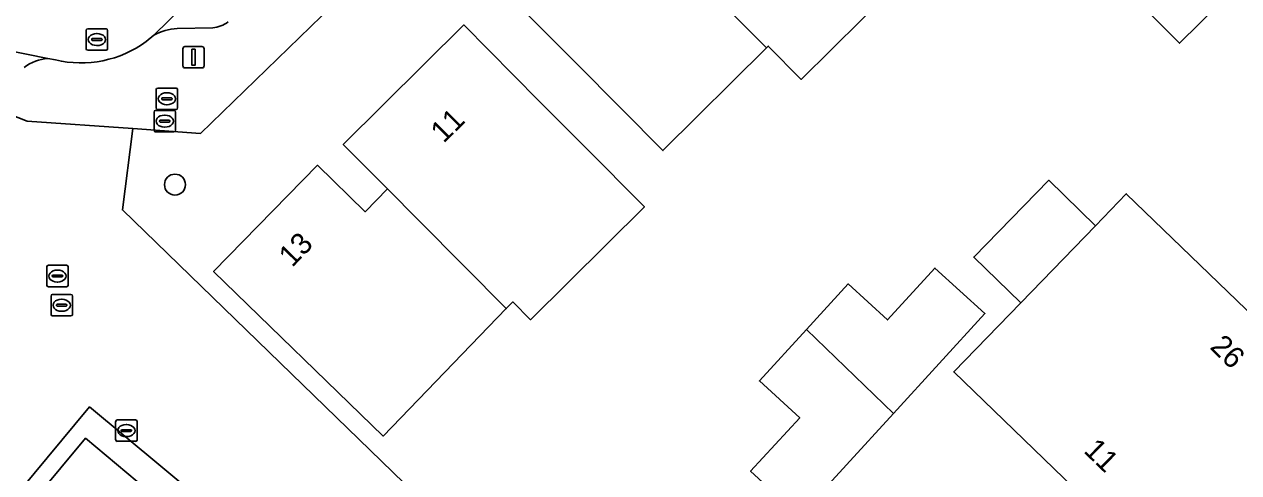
# Model space of a CAD drawing. Extents: x 161772 to 163126, y 383092 to 383917.
# Drawn here: x 162030.6 to 162087.2, y 383341.2 to 383362.1 of the extents above; entities that cross this region are included whole.
import ezdxf

# ---------------------------------------------------------------- set-up
doc = ezdxf.new("R2010")
doc.units = 0
for name, color, linetype in [('IMGEO_Boom', 7, 'Continuous'), ('IMGEO_Brandkraan', 7, 'Continuous'), ('IMGEO_Erf', 7, 'Continuous'), ('IMGEO_Kolk', 7, 'Continuous'), ('IMGEO_Lichtmast', 7, 'Continuous'), ('IMGEO_Pand', 7, 'Continuous'), ('IMGEO_Pand_nummerreeks', 7, 'Continuous'), ('IMGEO_Parkeervlak_open', 7, 'Continuous'), ('IMGEO_Rijbaan_lokaal_open', 7, 'Continuous'), ('IMGEO_Rioolput', 7, 'Continuous'), ('IMGEO_Voetpad_gesloten', 7, 'Continuous')]:
    doc.layers.add(name, color=color, linetype=linetype)

msp = doc.modelspace()

# ---------------------------------------------------------------- linework, layer by layer
at = {"layer": 'IMGEO_Boom'}
msp.add_circle((162037.581, 383354.637), 0.489, dxfattribs=at)
at = {"layer": 'IMGEO_Brandkraan'}
for p, q in [((162036.702, 383358.217), (162036.702, 383359.069)), ((162036.777, 383359.143), (162037.629, 383359.143)), ((162037.19, 383358.923), (162037.215, 383358.923)), ((162037.703, 383359.069), (162037.703, 383358.217)), ((162037.629, 383358.143), (162036.777, 383358.143)), ((162036.961, 383358.637), (162036.961, 383358.649)), ((162037.399, 383358.6), (162037.001, 383358.6)), ((162037.004, 383358.686), (162037.402, 383358.686)), ((162037.213, 383358.363), (162037.188, 383358.363)), ((162037.445, 383358.649), (162037.445, 383358.637)), ((162036.603, 383357.173), (162036.603, 383358.025)), ((162036.678, 383358.099), (162037.53, 383358.099)), ((162036.862, 383357.593), (162036.862, 383357.605)), ((162036.905, 383357.642), (162037.303, 383357.642)), ((162037.091, 383357.879), (162037.116, 383357.879)), ((162037.346, 383357.605), (162037.346, 383357.593)), ((162037.604, 383358.025), (162037.604, 383357.173)), ((162037.53, 383357.099), (162036.678, 383357.099)), ((162037.3, 383357.556), (162036.902, 383357.556)), ((162037.114, 383357.319), (162037.089, 383357.319))]:
    msp.add_line(p, q, dxfattribs=at)
for points in [[(162036.702, 383358.217), (162036.702, 383359.069)], [(162036.777, 383359.143), (162037.629, 383359.143)], [(162037.703, 383359.069), (162037.703, 383358.217)], [(162037.629, 383358.143), (162036.777, 383358.143)], [(162036.603, 383357.173), (162036.603, 383358.025)], [(162036.678, 383358.099), (162037.53, 383358.099)], [(162037.604, 383358.025), (162037.604, 383357.173)], [(162037.53, 383357.099), (162036.678, 383357.099)]]:
    msp.add_lwpolyline(points, dxfattribs=at)
for centre, radius, start, end in [((162036.779, 383359.067), 0.0765, 91.552, 178.448), ((162036.779, 383359.067), 0.0765, 91.552, 178.448), ((162037.627, 383359.067), 0.0765, 1.552, 88.448), ((162037.627, 383359.067), 0.0765, 1.552, 88.448), ((162036.779, 383358.219), 0.0765, 181.552, 268.448), ((162036.779, 383358.219), 0.0765, 181.552, 268.448), ((162037.001, 383358.646), 0.0403, 85.8775, 175.7526), ((162036.998, 383358.636), 0.0366, 178.938, 274.7102), ((162037.402, 383358.643), 0.043, 264.8664, 352.4533), ((162037.406, 383358.648), 0.0386, 1.7309, 96.639), ((162037.627, 383358.219), 0.0765, 271.552, 358.448), ((162037.627, 383358.219), 0.0765, 271.552, 358.448), ((162036.68, 383358.023), 0.0765, 91.552, 178.448), ((162036.68, 383358.023), 0.0765, 91.552, 178.448), ((162036.902, 383357.602), 0.0403, 85.8775, 175.7526), ((162036.899, 383357.592), 0.0366, 178.938, 274.7102), ((162037.303, 383357.599), 0.043, 264.8664, 352.4533), ((162037.307, 383357.604), 0.0386, 1.7309, 96.639), ((162037.528, 383358.023), 0.0765, 1.552, 88.448), ((162037.528, 383358.023), 0.0765, 1.552, 88.448), ((162036.68, 383357.175), 0.0765, 181.552, 268.448), ((162036.68, 383357.175), 0.0765, 181.552, 268.448), ((162037.528, 383357.175), 0.0765, 271.552, 358.448), ((162037.528, 383357.175), 0.0765, 271.552, 358.448)]:
    msp.add_arc(centre, radius, start, end, dxfattribs=at)
for centre, major_axis, ratio, start_param, end_param in [((162037.189, 383358.643), (-0.387, 0.002), 0.722429, 4.712389, 7.853982), ((162037.214, 383358.643), (-0.39, 0.002), 0.717154, 1.570796, 4.712389), ((162037.09, 383357.599), (-0.387, 0.002), 0.722429, 4.712389, 7.853982), ((162037.115, 383357.599), (-0.39, 0.002), 0.717154, 1.570796, 4.712389)]:
    msp.add_ellipse(centre, major_axis=major_axis, ratio=ratio, start_param=start_param, end_param=end_param, dxfattribs=at)
at = {"layer": 'IMGEO_Erf'}
for points in [[(162085.05, 383335.095), (162085.636, 383334.487), (162109.459, 383358.96), (162108.772, 383359.637), (162097.704, 383370.546), (162075.222, 383392.703), (162064.395, 383381.925), (162038.775, 383357.03), (162035.617, 383357.251), (162035.13, 383353.454), (162066.087, 383323.385), (162066.709, 383324.02), (162059.456, 383331.069), (162065.31, 383337.087), (162065.453, 383336.949), (162072.586, 383330.051), (162076.509, 383326.257)], [(162082.301, 383363.348), (162084.152, 383365.186), (162086.251, 383363.073), (162084.4, 383361.234)], [(162047.282, 383342.905), (162039.377, 383350.576), (162044.228, 383355.54), (162046.445, 383353.374), (162047.48, 383354.434), (162045.42, 383356.508), (162051.035, 383362.086), (162054.544, 383358.552), (162056.667, 383356.415), (162059.455, 383353.606), (162054.148, 383348.335), (162053.322, 383349.167), (162053.021, 383348.855)], [(162074.803, 383351.259), (162078.297, 383354.84), (162080.471, 383352.719), (162081.913, 383354.211), (162093.087, 383343.412), (162085.05, 383335.095), (162073.876, 383345.894), (162076.995, 383349.121)], [(162075.322, 383348.619), (162071.07, 383343.965), (162066.692, 383339.172), (162064.408, 383341.259), (162066.693, 383343.76), (162064.816, 383345.474), (162067.017, 383347.884), (162068.953, 383350.003), (162070.79, 383348.325), (162072.998, 383350.742)], [(162033.597, 383344.262), (162019.25, 383326.968), (162019.834, 383326.482), (162033.413, 383342.802), (162044.491, 383333.503), (162045.324, 383334.504)]]:
    msp.add_lwpolyline(points, close=True, dxfattribs=at)
msp.add_lwpolyline([(162071.005, 383363.761), (162066.764, 383359.549), (162065.225, 383361.098), (162065.147, 383361.021), (162060.32, 383356.227), (162058.387, 383358.173), (162056.238, 383360.337), (162052.746, 383363.85)], dxfattribs=at)
at = {"layer": 'IMGEO_Kolk'}
for p, q in [((162034.816, 383342.733), (162034.816, 383343.585)), ((162034.891, 383343.659), (162035.743, 383343.659)), ((162035.304, 383343.439), (162035.329, 383343.439)), ((162035.817, 383343.585), (162035.817, 383342.733)), ((162035.075, 383343.153), (162035.075, 383343.165)), ((162035.513, 383343.116), (162035.115, 383343.116)), ((162035.118, 383343.202), (162035.516, 383343.202)), ((162035.327, 383342.879), (162035.302, 383342.879)), ((162035.559, 383343.165), (162035.559, 383343.153)), ((162035.743, 383342.659), (162034.891, 383342.659))]:
    msp.add_line(p, q, dxfattribs=at)
for points in [[(162034.816, 383342.733), (162034.816, 383343.585)], [(162034.891, 383343.659), (162035.743, 383343.659)], [(162035.817, 383343.585), (162035.817, 383342.733)], [(162035.743, 383342.659), (162034.891, 383342.659)]]:
    msp.add_lwpolyline(points, dxfattribs=at)
for centre, radius, start, end in [((162034.893, 383343.583), 0.0765, 91.552, 178.448), ((162034.893, 383343.583), 0.0765, 91.552, 178.448), ((162035.741, 383343.583), 0.0765, 1.552, 88.448), ((162035.741, 383343.583), 0.0765, 1.552, 88.448), ((162035.115, 383343.162), 0.0403, 85.8775, 175.7526), ((162035.112, 383343.152), 0.0366, 178.938, 274.7102), ((162035.516, 383343.159), 0.043, 264.8664, 352.4533), ((162035.52, 383343.164), 0.0386, 1.7309, 96.639), ((162034.893, 383342.735), 0.0765, 181.552, 268.448), ((162034.893, 383342.735), 0.0765, 181.552, 268.448), ((162035.741, 383342.735), 0.0765, 271.552, 358.448), ((162035.741, 383342.735), 0.0765, 271.552, 358.448)]:
    msp.add_arc(centre, radius, start, end, dxfattribs=at)
for centre, major_axis, ratio, start_param, end_param in [((162035.303, 383343.159), (-0.387, 0.002), 0.722429, 4.712389, 7.853982), ((162035.328, 383343.159), (-0.39, 0.002), 0.717154, 1.570796, 4.712389)]:
    msp.add_ellipse(centre, major_axis=major_axis, ratio=ratio, start_param=start_param, end_param=end_param, dxfattribs=at)
at = {"layer": 'IMGEO_Lichtmast'}
for p, q in [((162037.947, 383360.18), (162037.947, 383360.98)), ((162037.947, 383360.98), (162037.947, 383360.18)), ((162038.047, 383361.08), (162038.837, 383361.08)), ((162038.837, 383361.08), (162038.047, 383361.08)), ((162038.937, 383360.98), (162038.937, 383360.18)), ((162038.937, 383360.18), (162038.937, 383360.98)), ((162038.837, 383360.08), (162038.047, 383360.08)), ((162038.047, 383360.08), (162038.837, 383360.08))]:
    msp.add_line(p, q, dxfattribs=at)
msp.add_lwpolyline([(162038.367, 383360.955), (162038.517, 383360.955), (162038.517, 383360.205), (162038.367, 383360.205), (162038.367, 383360.955)], dxfattribs=at)
for centre, start, end in [((162038.047, 383360.98), 90, 180), ((162038.047, 383360.98), 90, 180), ((162038.837, 383360.98), 0, 90), ((162038.837, 383360.98), 360, 90), ((162038.047, 383360.18), 180, 270), ((162038.047, 383360.18), 180, 270), ((162038.837, 383360.18), 270, 0), ((162038.837, 383360.18), 270, 0)]:
    msp.add_arc(centre, 0.1, start, end, dxfattribs=at)
at = {"layer": 'IMGEO_Pand'}
for points in [[(162068.261, 383367.9), (162062.636, 383373.673), (162057.56, 383368.632), (162065.147, 383361.021), (162065.225, 383361.098), (162066.764, 383359.549), (162071.005, 383363.761), (162071.659, 383364.412)], [(162057.56, 383368.632), (162052.746, 383363.85), (162056.238, 383360.337), (162058.387, 383358.173), (162060.32, 383356.227), (162065.147, 383361.021)], [(162086.251, 383363.073), (162084.152, 383365.186), (162082.301, 383363.348), (162084.4, 383361.234)], [(162056.667, 383356.415), (162054.544, 383358.552), (162051.035, 383362.086), (162045.42, 383356.508), (162047.48, 383354.434), (162048.944, 383352.961), (162051.052, 383350.838), (162053.021, 383348.855), (162053.322, 383349.167), (162054.148, 383348.335), (162059.455, 383353.606)], [(162051.052, 383350.838), (162048.944, 383352.961), (162047.48, 383354.434), (162046.445, 383353.374), (162044.228, 383355.54), (162039.377, 383350.576), (162047.282, 383342.905), (162053.021, 383348.855)], [(162080.471, 383352.719), (162078.297, 383354.84), (162074.803, 383351.259), (162076.995, 383349.121)], [(162081.913, 383354.211), (162080.471, 383352.719), (162076.995, 383349.121), (162073.876, 383345.894), (162085.05, 383335.095), (162093.087, 383343.412)], [(162071.07, 383343.965), (162075.322, 383348.619), (162072.998, 383350.742), (162070.79, 383348.325), (162068.953, 383350.003), (162067.017, 383347.884)], [(162071.07, 383343.965), (162067.017, 383347.884), (162064.816, 383345.474), (162066.693, 383343.76), (162064.408, 383341.259), (162066.692, 383339.172)], [(162042.175, 383330.708), (162042.699, 383331.34), (162044.491, 383333.503), (162033.413, 383342.802), (162019.834, 383326.482), (162024.353, 383322.748), (162026.638, 383320.859), (162031.017, 383317.241), (162032.919, 383319.537)]]:
    msp.add_lwpolyline(points, close=True, dxfattribs=at)
at = {"layer": 'IMGEO_Parkeervlak_open'}
for points in [[(162069.402, 383393.751), (162036.595, 383361.608)], [(162031.651, 383360.514), (161994.524, 383368.077), (161993.858, 383368.213)], [(162037.678, 383361.928), (162039.344, 383361.959)]]:
    msp.add_lwpolyline(points, dxfattribs=at)
for centre, radius, start, end in [((162039.229, 383363.336), 1.382, 274.7736, 306.7612), ((162037.889, 383359.22), 2.716, 94.4626, 118.4597), ((162031.784, 383358.483), 2.036, 93.7359, 127.0196)]:
    msp.add_arc(centre, radius, start, end, dxfattribs=at)
at = {"layer": 'IMGEO_Rijbaan_lokaal_open'}
for points in [[(162036.245, 383361.319), (162036.595, 383361.608), (162069.402, 383393.751)], [(162031.731, 383363.861), (162026.624, 383364.907), (162022.901, 383365.67), (161995.201, 383371.459), (161994.524, 383368.077), (162031.651, 383360.514), (162032.009, 383360.453)], [(162066.087, 383323.385), (162035.13, 383353.454), (162035.617, 383357.251), (162030.694, 383357.595), (162029.829, 383357.939), (162027.077, 383344.535), (162026.145, 383344.722), (162012.665, 383328.248)]]:
    msp.add_lwpolyline(points, dxfattribs=at)
msp.add_lwpolyline([(162021.848, 383319.686), (162024.353, 383322.748), (162019.834, 383326.482), (162019.25, 383326.968), (162033.597, 383344.262), (162045.324, 383334.504), (162044.491, 383333.503), (162042.699, 383331.34), (162042.175, 383330.708), (162042.065, 383329.499), (162041.991, 383329.019), (162041.464, 383328.268), (162040.242, 383327.129), (162039.15, 383325.806), (162037.784, 383323.976), (162036.394, 383322.553), (162035.787, 383321.748), (162035.018, 383320.343), (162034.547, 383319.954), (162034.107, 383319.606), (162032.919, 383319.537), (162031.017, 383317.241), (162026.638, 383320.859), (162024.174, 383317.796)], close=True, dxfattribs=at)
msp.add_arc((162033.188, 383365.477), 5.161, 256.7896, 306.3189, dxfattribs=at)
at = {"layer": 'IMGEO_Rioolput'}
for p, q in [((162033.44, 383360.98), (162033.44, 383361.832)), ((162033.515, 383361.906), (162034.367, 383361.906)), ((162033.928, 383361.686), (162033.953, 383361.686)), ((162034.441, 383361.832), (162034.441, 383360.98)), ((162033.699, 383361.4), (162033.699, 383361.412)), ((162034.137, 383361.363), (162033.739, 383361.363)), ((162033.742, 383361.449), (162034.14, 383361.449)), ((162033.951, 383361.126), (162033.926, 383361.126)), ((162034.183, 383361.412), (162034.183, 383361.4)), ((162034.367, 383360.906), (162033.515, 383360.906)), ((162031.604, 383349.945), (162031.604, 383350.797)), ((162031.679, 383350.871), (162032.531, 383350.871)), ((162032.605, 383350.797), (162032.605, 383349.945)), ((162031.863, 383350.365), (162031.863, 383350.377)), ((162032.301, 383350.328), (162031.903, 383350.328)), ((162031.906, 383350.414), (162032.304, 383350.414)), ((162032.092, 383350.651), (162032.117, 383350.651)), ((162032.347, 383350.377), (162032.347, 383350.365)), ((162032.531, 383349.871), (162031.679, 383349.871)), ((162032.115, 383350.091), (162032.09, 383350.091)), ((162031.803, 383348.583), (162031.803, 383349.435)), ((162031.878, 383349.509), (162032.73, 383349.509)), ((162032.291, 383349.289), (162032.316, 383349.289)), ((162032.804, 383349.435), (162032.804, 383348.583)), ((162032.73, 383348.509), (162031.878, 383348.509)), ((162032.062, 383349.003), (162032.062, 383349.015)), ((162032.5, 383348.966), (162032.102, 383348.966)), ((162032.105, 383349.052), (162032.503, 383349.052)), ((162032.314, 383348.729), (162032.289, 383348.729)), ((162032.546, 383349.015), (162032.546, 383349.003))]:
    msp.add_line(p, q, dxfattribs=at)
for points in [[(162033.44, 383360.98), (162033.44, 383361.832)], [(162033.515, 383361.906), (162034.367, 383361.906)], [(162034.441, 383361.832), (162034.441, 383360.98)], [(162034.367, 383360.906), (162033.515, 383360.906)], [(162031.604, 383349.945), (162031.604, 383350.797)], [(162031.679, 383350.871), (162032.531, 383350.871)], [(162032.605, 383350.797), (162032.605, 383349.945)], [(162032.531, 383349.871), (162031.679, 383349.871)], [(162031.803, 383348.583), (162031.803, 383349.435)], [(162031.878, 383349.509), (162032.73, 383349.509)], [(162032.804, 383349.435), (162032.804, 383348.583)], [(162032.73, 383348.509), (162031.878, 383348.509)]]:
    msp.add_lwpolyline(points, dxfattribs=at)
for centre, radius, start, end in [((162033.517, 383361.83), 0.0765, 91.552, 178.448), ((162033.517, 383361.83), 0.0765, 91.552, 178.448), ((162034.365, 383361.83), 0.0765, 1.552, 88.448), ((162034.365, 383361.83), 0.0765, 1.552, 88.448), ((162033.517, 383360.982), 0.0765, 181.552, 268.448), ((162033.517, 383360.982), 0.0765, 181.552, 268.448), ((162033.739, 383361.409), 0.0403, 85.8775, 175.7526), ((162033.736, 383361.399), 0.0366, 178.938, 274.7102), ((162034.14, 383361.406), 0.043, 264.8664, 352.4533), ((162034.144, 383361.411), 0.0386, 1.7309, 96.639), ((162034.365, 383360.982), 0.0765, 271.552, 358.448), ((162034.365, 383360.982), 0.0765, 271.552, 358.448), ((162031.681, 383350.795), 0.0765, 91.552, 178.448), ((162031.681, 383350.795), 0.0765, 91.552, 178.448), ((162032.529, 383350.795), 0.0765, 1.552, 88.448), ((162032.529, 383350.795), 0.0765, 1.552, 88.448), ((162031.903, 383350.374), 0.0403, 85.8775, 175.7526), ((162031.9, 383350.364), 0.0366, 178.938, 274.7102), ((162032.304, 383350.371), 0.043, 264.8664, 352.4533), ((162032.308, 383350.376), 0.0386, 1.7309, 96.639), ((162031.681, 383349.947), 0.0765, 181.552, 268.448), ((162031.681, 383349.947), 0.0765, 181.552, 268.448), ((162032.529, 383349.947), 0.0765, 271.552, 358.448), ((162032.529, 383349.947), 0.0765, 271.552, 358.448), ((162031.88, 383349.433), 0.0765, 91.552, 178.448), ((162031.88, 383349.433), 0.0765, 91.552, 178.448), ((162032.728, 383349.433), 0.0765, 1.552, 88.448), ((162032.728, 383349.433), 0.0765, 1.552, 88.448), ((162031.88, 383348.585), 0.0765, 181.552, 268.448), ((162031.88, 383348.585), 0.0765, 181.552, 268.448), ((162032.102, 383349.012), 0.0403, 85.8775, 175.7526), ((162032.099, 383349.002), 0.0366, 178.938, 274.7102), ((162032.503, 383349.009), 0.043, 264.8664, 352.4533), ((162032.507, 383349.014), 0.0386, 1.7309, 96.639), ((162032.728, 383348.585), 0.0765, 271.552, 358.448), ((162032.728, 383348.585), 0.0765, 271.552, 358.448)]:
    msp.add_arc(centre, radius, start, end, dxfattribs=at)
for centre, major_axis, ratio, start_param, end_param in [((162033.927, 383361.406), (-0.387, 0.002), 0.722429, 4.712389, 7.853982), ((162033.952, 383361.406), (-0.39, 0.002), 0.717154, 1.570796, 4.712389), ((162032.091, 383350.371), (-0.387, 0.002), 0.722429, 4.712389, 7.853982), ((162032.116, 383350.371), (-0.39, 0.002), 0.717154, 1.570796, 4.712389), ((162032.29, 383349.009), (-0.387, 0.002), 0.722429, 4.712389, 7.853982), ((162032.315, 383349.009), (-0.39, 0.002), 0.717154, 1.570796, 4.712389)]:
    msp.add_ellipse(centre, major_axis=major_axis, ratio=ratio, start_param=start_param, end_param=end_param, dxfattribs=at)
at = {"layer": 'IMGEO_Voetpad_gesloten'}
for points in [[(161990.373, 383368.718), (161989.921, 383365.674), (162000.777, 383363.851), (162008.596, 383362.237), (162022.202, 383359.485), (162028.881, 383358.134), (162029.829, 383357.939), (162030.694, 383357.595), (162035.617, 383357.251), (162038.775, 383357.03), (162064.395, 383381.925)], [(162036.595, 383361.608), (162036.245, 383361.319)], [(162039.344, 383361.959), (162037.678, 383361.928)], [(162032.009, 383360.453), (162031.651, 383360.514)]]:
    msp.add_lwpolyline(points, dxfattribs=at)
for centre, radius, start, end in [((162039.229, 383363.336), 1.382, 274.7736, 306.7612), ((162037.889, 383359.22), 2.716, 94.4626, 118.4597), ((162033.188, 383365.477), 5.161, 256.7896, 306.3189), ((162031.784, 383358.483), 2.036, 93.7359, 127.0196)]:
    msp.add_arc(centre, radius, start, end, dxfattribs=at)

# ---------------------------------------------------------------- texts
at = {"layer": 'IMGEO_Pand_nummerreeks'}
for s, rotation, p in [('11', 44.811, (162050.098, 383356.532)), ('13', 45.659, (162043.035, 383350.743)), ('26', 315.7791, (162085.767, 383347.014)), ('11', 315.7791, (162079.882, 383342.18))]:
    msp.add_text(s, height=1, rotation=rotation, dxfattribs=at).set_placement(p)

doc.saveas('drawing.dxf')
